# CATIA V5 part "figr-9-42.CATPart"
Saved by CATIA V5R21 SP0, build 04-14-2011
Part number: Part1
Bounding box of the stored display mesh (mm): x -60 to 60, y -70.383 to 65.913, z 0 to 125
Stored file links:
  D:\CATIA V5R21 E-RESOURCES\CATIA-V5R21\catia-v5r21-prt\c09-catia-v5r20-prt\c09-catia-v5r21-figr-9-42.CATPart
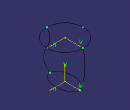
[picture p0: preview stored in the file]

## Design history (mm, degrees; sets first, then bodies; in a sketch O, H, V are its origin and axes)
Set1
  Plane1: type Offset, RefPlane xy-plane, Offset 125
Body1 (main body)
  Sketch1 on xy-plane, origin (0, 0, 0), H (1, 0, 0), V (0, 1, 0)
    ellipse A1 centre (0, 0) semi-axes 50, 30 rotation 270
    point P1 (30, 0)
    coincidence: P1 H, A1 P1
  Sketch2 on Plane1, origin (0, 0, 125), H (1, 0, 0), V (0, 1, 0)
    circle A1 centre (0, 0) radius 60
  Sketch3 on yz-plane, origin (0, 0, 0), H (0, 1, 0), V (0, 0, 1)
    arc A1 centre (-129.6632, 77.2731) radius 195.5761 from (50, 0) to (60, 125) ccw
    point P2 (50, 0)
    point P3 (60, 125)
    reference projected line E1 (-50, 0) -> (50, 0) from edge of Sketch1
    reference projected line E2 (-60, 125) -> (60, 125) from edge of Sketch2
    coincidence: P2 H, P2 E1, P3 E2
  Sketch4 on yz-plane, origin (0, 0, 0), H (0, 1, 0), V (0, 0, 1)
    spline S1 through (-50, 0) (-70, 40) (-50, 100) (-60, 125)
    reference projected line E1 (-60, 125) -> (60, 125) from edge of Sketch2
    reference projected line E2 (-50, 0) -> (50, 0) from edge of Sketch1
    point P1 (-60, 125)
    point P2 (-50, 0)
    coincidence: P1 E1, P2 E2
